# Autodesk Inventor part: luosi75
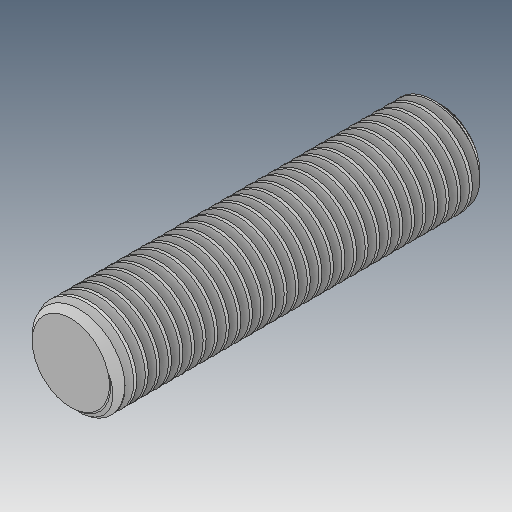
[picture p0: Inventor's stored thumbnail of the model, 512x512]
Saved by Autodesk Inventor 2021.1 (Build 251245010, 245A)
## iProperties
Created: 2018-07
Part Number: luosi75
Material: Ogólny
Document SubType Name: Modeling
Designer: user
Density: 1 g/cm^3
Appearance: Domyślna
Author: user
Revision Number: ÈÎºÎ
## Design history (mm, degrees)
feature "ÇÐ³ý-É¨Ãè1"
node "Bryła1"
